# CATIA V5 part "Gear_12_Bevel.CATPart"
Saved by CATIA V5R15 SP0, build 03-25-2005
Part number: Gear_12_Bevel
Material "Crisp Green": density 7860 kg/m3, Young's modulus 2e+11 Pa, Poisson ratio 0.266
Bounding box of the stored display mesh (mm): x -63 to 63, y -62.995 to 62.995, z -34 to 5
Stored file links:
  E:\#01 CATIA Lecture Materials\#06 DMU\#11 DMU Page01 KIN EX11\Gear_12_Bevel.CATPart
  C:\Program Files\Dassault Systemes\B20\win_b64\startup\materials\Catalog.CATMaterial
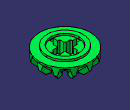
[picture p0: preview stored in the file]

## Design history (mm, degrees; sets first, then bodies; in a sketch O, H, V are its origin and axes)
Body1 (main body), material "Crisp Green"
  Sketch1 on xy-plane, origin (0, 0, 0), H (1, 0, 0), V (0, 1, 0)
    circle A1 centre (0, 0) radius 45
    radius A1 = 45
  Pad1: profile Sketch1, direction (0, 0, 1), length 5
  Sketch2 on start face of Pad1, origin (0, 0, 0), H (1, 0, 0), V (0, -1, 0)
    circle A1 centre (0, 0) radius 63
    radius A1 = 63
  Pad2: profile Sketch2, direction (0, 0, -1), length 4
  Sketch3 on end face of Pad2, origin (0, 0, -4), H (1, 0, 0), V (0, -1, 0)
    circle A1 centre (0, 0) radius 38.5
    radius A1 = 38.5
  Pad3: profile Sketch3, direction (0, 0, -1), length 30
  Sketch4 on end face of Pad3, origin (0, 0, -34), H (1, 0, 0), V (0, -1, 0)
    line L1 (9.25, 21.9289) -> (9.25, 9.25)
    line L2 (-9.25, -21.9289) -> (-9.25, -9.25)
    point P3 (-21.9289, 9.25)
    line L3 (-21.9289, 9.25) -> (-9.25, 9.25)
    line L4 (21.9289, -9.25) -> (9.25, -9.25)
    point P6 (-21.9289, -9.25)
    arc A1 centre (0, 0) radius 23.8 from (9.25, 21.9289) to (4.5, 23.3707) ccw
    arc A2 centre (0, 0) radius 23.8 from (-21.9289, 9.25) to (-23.3707, 4.5) ccw
    line L5 (-9.25, 9.25) -> (-9.25, 21.9289)
    point P8 (-9.25, -9.25)
    line L6 (9.25, 9.25) -> (21.9289, 9.25)
    line L7 (9.25, -9.25) -> (9.25, -21.9289)
    line L8 (-9.25, -9.25) -> (-21.9289, -9.25)
    point P11 (-9.25, -21.9289)
    arc A3 centre (0, 0) radius 23.8 from (21.9289, -9.25) to (23.3707, -4.5) ccw
    arc A4 centre (0, 0) radius 23.8 from (-9.25, -21.9289) to (-4.5, -23.3707) ccw
    line L9 (-4.5, 33.5) -> (4.5, 33.5)
    line L10 (4.5, 33.5) -> (4.5, 23.3707)
    line L11 (4.5, -33.5) -> (-4.5, -33.5)
    line L12 (-4.5, -33.5) -> (-4.5, -23.3707)
    reference projected circle E1 centre (0, 0) radius 38.5 from edge [face of Pad3 from Sketch3.A1 | end face of Pad3]
    point P17 (4.5, -23.3707)
    line L13 (4.5, -23.3707) -> (4.5, -33.5)
    point P19 (-4.5, 23.3707)
    line L14 (-4.5, 23.3707) -> (-4.5, 33.5)
    arc A5 centre (0, 0) radius 23.8 from (4.5, -23.3707) to (9.25, -21.9289) ccw
    arc A6 centre (0, 0) radius 23.8 from (-4.5, 23.3707) to (-9.25, 21.9289) ccw
    line L15 (-33.5, 4.5) -> (-23.3707, 4.5)
    line L16 (33.5, 4.5) -> (33.5, -4.5)
    line L17 (33.5, -4.5) -> (23.3707, -4.5)
    line L18 (-33.5, -4.5) -> (-33.5, 4.5)
    reference projected circle E2 centre (0, 0) radius 38.5 from edge [face of Pad3 from Sketch3.A1 | end face of Pad3]
    arc A7 centre (0, 0) radius 23.8 from (23.3707, 4.5) to (21.9289, 9.25) ccw
    point P26 (23.3707, 4.5)
    line L19 (23.3707, 4.5) -> (33.5, 4.5)
    line L20 (-23.3707, -4.5) -> (-33.5, -4.5)
    point P28 (-23.3707, -4.5)
    arc A8 centre (0, 0) radius 23.8 from (-23.3707, -4.5) to (-21.9289, -9.25) ccw
    radius A1 = 23.8
    distance L3 L4 = 18.5
    distance L1 L2 = 18.5
    distance L9 E1 = 5
    distance L10 L14 = 9
    distance L15 L17 = 9
    distance L16 E2 = 5
    vertical: L1 V, L2 V, L5 V, L7 V, L10 V, L12 V, L13 V, L14 V, L16 V, L18 V
    horizontal: L3 H, L4 H, L6 H, L8 H, L9 H, L11 H, L15 H, L17 H, L19 H, L20 H
    symmetry: L4 L3 H, L1 L2 V, L10 L12 V, L11 L9 H, L15 L17 H, L16 L18 V
    coincidence: P3 A1, P6 A1, A1 A2, L4 P8, L2 L5, L3 L6, L1 L7, L4 L8, A2 P11, A2 A3, A2 A4, A4 P17, L10 L13, A1 P19, L12 L14, A4 A5, A1 A6, L15 P26, A3 A7, L15 L19, A2 P28, L17 L20, A2 A8
  Pocket1: profile Sketch4, direction (0, 0, 1), through (limit type 3)
  Fillet1: radius 3, on edge [face of Pocket1 from Sketch4.L2 | face of Pocket1 from Sketch4.L8]; edge [face of Pocket1 from Sketch4.L3 | face of Pocket1 from Sketch4.L5]; edge [face of Pocket1 from Sketch4.L1 | face of Pocket1 from Sketch4.L6]; edge [face of Pocket1 from Sketch4.L4 | face of Pocket1 from Sketch4.L7]
  Sketch5 on end face of Pad2, origin (0, 0, -4), H (1, 0, 0), V (0, -1, 0)
    point P1 (-7.5, 62.552)
    line L1 (7.5, 62.552) -> (7.5, 37.7624)
    line L2 (-7.5, 37.7624) -> (-7.5, 62.552)
    point P2 (7.5, 62.552)
    point P3 (7.5, 37.7624)
    point P4 (-7.5, 37.7624)
    reference projected circle E1 centre (0, 0) radius 63 from edge [face of Pad2 from Sketch2.A1 | end face of Pad2]
    reference projected circle E2 centre (0, 0) radius 38.5 from edge [face of Pad3 from Sketch3.A1 | end face of Pad3]
    arc A1 centre (0, 0) radius 63 from (-7.5, 62.552) to (7.5, 62.552) cw
    point P6 (0, 63)
    reference projected circle E3 centre (0, 0) radius 63 from edge [face of Pad2 from Sketch2.A1 | end face of Pad2]
    reference projected circle E4 centre (0, 0) radius 63 from edge [face of Pad2 from Sketch2.A1 | end face of Pad2]
    reference projected circle E5 centre (0, 0) radius 63 from edge [face of Pad2 from Sketch2.A1 | end face of Pad2]
    arc A2 centre (0, 0) radius 38.5 from (-7.5, 37.7624) to (7.5, 37.7624) cw
    point P8 (0, 38.5)
    reference projected circle E6 centre (0, 0) radius 38.5 from edge [face of Pad3 from Sketch3.A1 | end face of Pad3]
    reference projected circle E7 centre (0, 0) radius 38.5 from edge [face of Pad3 from Sketch3.A1 | end face of Pad3]
    reference projected circle E8 centre (0, 0) radius 38.5 from edge [face of Pad3 from Sketch3.A1 | end face of Pad3]
    distance L1 L2 = 15
    vertical: L1 V, L2 V
    coincidence: P2 E1, P3 E2, A1 P6, P6 V, P1 E3, A1 E4, A2 P8, P8 V, P4 E6, A2 E7
    symmetry: L1 L2 V
    concentricity: A1 E5, A2 E8
  Pad4: profile Sketch5, direction (0, 0, -1), up to end face of Pad3
  Draft1: Angle 5, Neutral end face of Pad2, PullDir end face of Pad2, SupportToDraft (face of Pad4 from Sketch5.L1; face of Pad4 from Sketch5.L2)
  Chamfer1: length 14, angle 45, on edge [face of Pad2 | face of Pad3]
  Chamfer2: length 10, angle 20, on edge [face of Pad4 from Sketch5.L1 | face of Chamfer1]; edge [face of Pad4 from Sketch5.L2 | face of Chamfer1]
  CircPattern1: of Pad4, Draft1, Chamfer1, Chamfer2, instances 12, angular step 30 {= 360.0*1 deg/CircPattern1.AngularNumber}, axis from face of Pad3 from Sketch3.A1
  Sketch6 on end face of Pad1, origin (0, 0, 5), H (1, 0, 0), V (0, 1, 0)
    circle A1 centre (0, 0) radius 35
    radius A1 = 35
  Pocket2: profile Sketch6, direction (0, 0, -1), up to start face of Pad2
  Sketch7 on face of Pad3, origin (0, 0, -34), H (1, 0, 0), V (0, -1, 0)
    point P1 (15.896, 37.69)
    axis line L1 (0, 0) -> (60.1524, 60.1524)
    point P3 (16.4932, 23.8119)
    line L2 (16.4932, 23.8119) -> (23.3172, 30.6359)
    point P4 (23.3172, 30.6359)
    point P5 (23.8119, 16.4932)
    line L3 (23.8119, 16.4932) -> (30.6359, 23.3172)
    point P6 (30.6359, 23.3172)
    construction arc A1 centre (0, 0) radius 38.5 from (23.3172, 30.6359) to (30.6359, 23.3172) cw
    point P8 (23.3172, 30.6359)
    point P9 (27.2236, 27.2236)
    reference projected circle E1 centre (0, 0) radius 38.5 from edge [face of Pad3 from Sketch3.A1 | face of Pad3]
    reference projected circle E2 centre (0, 0) radius 38.5 from edge [face of Pad3 from Sketch3.A1 | face of Pad3]
    reference projected line E3 (23.3172, 30.6359) -> (35.6277, 51.9583) from edge [face of CircPattern1 | face of Pad3]
    arc A2 centre (20.1525, 20.1525) radius 5.1751 from (16.4932, 23.8119) to (23.8119, 16.4932) ccw
    point P10 (20.1525, 20.1525)
    point P11 (16.4932, 16.4932)
    line L4 (23.3172, 30.6359) -> (32.0561, 39.3748)
    point P12 (32.0561, 39.3748)
    line L5 (32.0561, 39.3748) -> (39.3748, 32.0561)
    point P13 (39.3748, 32.0561)
    line L6 (39.3748, 32.0561) -> (30.6359, 23.3172)
    point P14 (15.896, -37.69)
    point P15 (16.4932, -23.8119)
    point P16 (23.3172, -30.6359)
    point P17 (23.8119, -16.4932)
    point P18 (30.6359, -23.3172)
    point P19 (23.3172, -30.6359)
    construction arc A3 centre (0, 0) radius 38.5 from (23.3172, -30.6359) to (30.6359, -23.3172) ccw
    point P21 (27.2236, -27.2236)
    point P23 (16.4932, -16.4932)
    point P24 (32.0561, -39.3748)
    point P25 (39.3748, -32.0561)
    line L7 (16.4932, -23.8119) -> (23.3172, -30.6359)
    line L8 (23.8119, -16.4932) -> (30.6359, -23.3172)
    arc A4 centre (20.1525, -20.1525) radius 5.1751 from (16.4932, -23.8119) to (23.8119, -16.4932) cw
    line L9 (23.3172, -30.6359) -> (32.0561, -39.3748)
    line L10 (32.0561, -39.3748) -> (39.3748, -32.0561)
    line L11 (39.3748, -32.0561) -> (30.6359, -23.3172)
    point P26 (-15.896, 37.69)
    point P27 (-16.4932, 23.8119)
    point P28 (-23.3172, 30.6359)
    point P29 (-23.8119, 16.4932)
    point P30 (-30.6359, 23.3172)
    point P31 (-23.3172, 30.6359)
    construction arc A5 centre (0, 0) radius 38.5 from (-23.3172, 30.6359) to (-30.6359, 23.3172) ccw
    point P33 (-27.2236, 27.2236)
    point P35 (-16.4932, 16.4932)
    point P36 (-32.0561, 39.3748)
    point P37 (-39.3748, 32.0561)
    point P38 (-15.896, -37.69)
    point P39 (-16.4932, -23.8119)
    point P40 (-23.3172, -30.6359)
    point P41 (-23.8119, -16.4932)
    point P42 (-30.6359, -23.3172)
    point P43 (-23.3172, -30.6359)
    construction arc A6 centre (0, 0) radius 38.5 from (-23.3172, -30.6359) to (-30.6359, -23.3172) cw
    point P45 (-27.2236, -27.2236)
    point P47 (-16.4932, -16.4932)
    point P48 (-32.0561, -39.3748)
    point P49 (-39.3748, -32.0561)
    line L12 (-16.4932, 23.8119) -> (-23.3172, 30.6359)
    line L13 (-23.8119, 16.4932) -> (-30.6359, 23.3172)
    arc A7 centre (-20.1525, 20.1525) radius 5.1751 from (-16.4932, 23.8119) to (-23.8119, 16.4932) cw
    line L14 (-23.3172, 30.6359) -> (-32.0561, 39.3748)
    line L15 (-32.0561, 39.3748) -> (-39.3748, 32.0561)
    line L16 (-39.3748, 32.0561) -> (-30.6359, 23.3172)
    line L17 (-16.4932, -23.8119) -> (-23.3172, -30.6359)
    line L18 (-23.8119, -16.4932) -> (-30.6359, -23.3172)
    arc A8 centre (-20.1525, -20.1525) radius 5.1751 from (-16.4932, -23.8119) to (-23.8119, -16.4932) ccw
    line L19 (-23.3172, -30.6359) -> (-32.0561, -39.3748)
    line L20 (-32.0561, -39.3748) -> (-39.3748, -32.0561)
    line L21 (-39.3748, -32.0561) -> (-30.6359, -23.3172)
    angle L1 H = 45
    distance P10 A1 = 10
    distance L3 L2 = 10.3502
    distance L5 P10 = 22.0093
    parallelism: L2 L1, L3 L1
    coincidence: A1 P9, P9 L1, A1 E2, E3 P4, A2 P11, P11 L1, P12 L2
    concentricity: A1 E1
    symmetry: L2 L3 L1, P1 P14 H, P3 P15 H, P4 P16 H, P5 P17 H, P6 P18 H, P8 P19 H, A1 A3 H, P9 P21 H, P11 P23 H, P12 P24 H, P13 P25 H, L2 L7 H, L3 L8 H, A2 A4 H, L4 L9 H, L5 L10 H, L6 L11 H, P1 P26 V, P3 P27 V, P4 P28 V, P5 P29 V, P6 P30 V, P8 P31 V, A1 A5 V, P9 P33 V, P11 P35 V, P12 P36 V, P13 P37 V, P14 P38 V, P15 P39 V, P16 P40 V, P17 P41 V, P18 P42 V, P19 P43 V, A3 A6 V, P21 P45 V, P23 P47 V, P24 P48 V, P25 P49 V, L2 L12 V, L3 L13 V, A2 A7 V, L4 L14 V, L5 L15 V, L6 L16 V, L7 L17 V, L8 L18 V, A4 A8 V, L9 L19 V, L10 L20 V, L11 L21 V
    tangency: A2 L3, A2 L2
    perpendicularity: L5 L3, L5 L4, L5 L6
  Pocket3: profile Sketch7, direction (0, 0, 1), up to end face of Pad2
